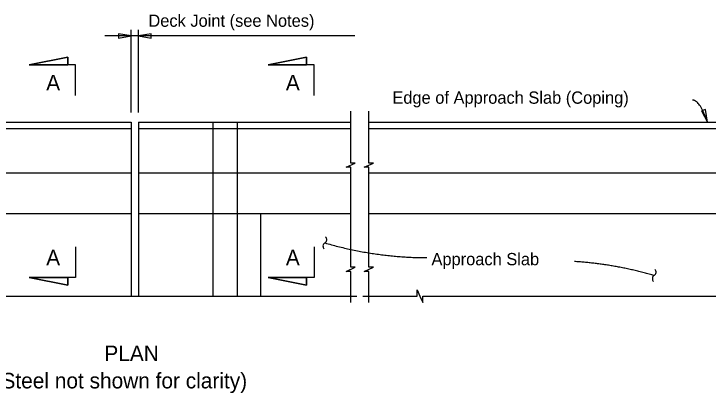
# Model space of a CAD drawing. Extents: x 0.5 to 40.8, y 1 to 25.8.
# Drawn here: x 18.01 to 29.41, y 19.47 to 25.71 of the extents above; entities that cross this region are included whole.
import ezdxf

# ---------------------------------------------------------------- set-up
doc = ezdxf.new("R2010")
doc.units = 0
for name, color, linetype in [('Dimension', 7, 'Continuous'), ('TextStructures', 7, 'Continuous'), ('TrafBarrierConc', 7, 'Continuous')]:
    doc.layers.add(name, color=color, linetype=linetype)

msp = doc.modelspace()

# ---------------------------------------------------------------- linework, layer by layer
at = {"layer": 'Dimension'}
for p, q in [((19.93, 24.083), (19.93, 25.443)), ((20.053, 24.083), (20.053, 25.443)), ((23.605, 25.342), (19.499, 25.342)), ((18.258, 24.868), (18.89, 24.995)), ((18.89, 24.995), (18.89, 24.868)), ((22.179, 24.868), (22.812, 24.995)), ((22.812, 24.995), (22.812, 24.868)), ((19.017, 24.868), (18.258, 24.868)), ((19.017, 24.362), (19.017, 24.868)), ((22.939, 24.868), (22.179, 24.868)), ((22.939, 24.362), (22.939, 24.868)), ((19.017, 21.876), (19.017, 21.369)), ((22.939, 21.876), (22.939, 21.369)), ((19.017, 21.369), (18.258, 21.369)), ((18.258, 21.369), (18.89, 21.243)), ((18.89, 21.243), (18.89, 21.369)), ((22.939, 21.369), (22.179, 21.369)), ((22.179, 21.369), (22.812, 21.243)), ((22.812, 21.243), (22.812, 21.369))]:
    msp.add_line(p, q, dxfattribs=at)
for points in [[(19.93, 25.342), (19.722, 25.377), (19.722, 25.306)], [(20.053, 25.342), (20.261, 25.306), (20.261, 25.377)], [(18.89, 24.868), (18.89, 24.995), (18.258, 24.868)], [(22.812, 24.868), (22.812, 24.995), (22.179, 24.868)], [(29.395, 23.924), (29.361, 24.132), (29.295, 24.11)], [(18.89, 21.369), (18.89, 21.243), (18.258, 21.369)], [(22.812, 21.369), (22.812, 21.243), (22.179, 21.369)]]:
    msp.add_lwpolyline(points, close=True, dxfattribs=at)
for points in [[(23.537, 22.14), (23.537, 23.186), (23.46, 23.186), (23.61, 23.252), (23.537, 23.252), (23.537, 24.107)], [(23.837, 22.14), (23.837, 23.186), (23.76, 23.186), (23.91, 23.252), (23.837, 23.252), (23.837, 24.107)], [(23.537, 20.963), (23.537, 21.472), (23.46, 21.472), (23.61, 21.539), (23.537, 21.539), (23.537, 22.14)], [(23.837, 20.963), (23.837, 21.472), (23.76, 21.472), (23.91, 21.539), (23.837, 21.539), (23.837, 22.14)], [(11.857, 21.063), (14.406, 21.063), (14.406, 21.167), (14.451, 21.063), (14.496, 20.96), (14.496, 21.063), (19.93, 21.063)], [(23.737, 21.063), (24.629, 21.063), (24.629, 21.167), (24.674, 21.063), (24.719, 20.96), (24.719, 21.063), (30.61, 21.063)], [(19.93, 21.063), (23.637, 21.063)]]:
    msp.add_lwpolyline(points, dxfattribs=at)
for centre, start, end in [((23.085, 21.992), 298.0989, 49.8261), ((23.141, 21.886), 118.0989, 229.8261), ((28.493, 21.458), 298.0989, 49.8261), ((28.549, 21.352), 118.0989, 229.8261)]:
    msp.add_arc(centre, 0.0596, start, end, dxfattribs=at)
for points in [[(29.395, 23.924), (29.272, 24.287), (29.149, 24.287)], [(23.113, 21.94), (23.95, 21.698), (24.788, 21.698)], [(28.521, 21.404), (27.865, 21.593), (27.209, 21.634)]]:
    msp.add_open_spline(points, degree=2, dxfattribs=at)
at = {"layer": 'TrafBarrierConc'}
for p, q in [((11.931, 23.924), (19.93, 23.924)), ((19.93, 23.924), (19.93, 21.063)), ((20.053, 23.924), (20.053, 21.063)), ((20.053, 23.924), (23.537, 23.924)), ((21.273, 23.924), (21.273, 21.063)), ((21.67, 23.924), (21.67, 21.063)), ((23.837, 23.924), (39.818, 23.924)), ((11.931, 23.82), (19.93, 23.82)), ((20.053, 23.82), (23.537, 23.82)), ((23.837, 23.82), (33.151, 23.82)), ((11.931, 23.091), (19.93, 23.091)), ((20.053, 23.091), (23.537, 23.091)), ((23.837, 23.091), (33.151, 23.091)), ((11.931, 22.424), (19.93, 22.424)), ((20.053, 22.424), (23.537, 22.424)), ((22.053, 22.424), (22.053, 21.063)), ((23.837, 22.424), (36.818, 22.424))]:
    msp.add_line(p, q, dxfattribs=at)

# ---------------------------------------------------------------- texts
at = {"layer": 'Dimension'}
for s, p in [('PLAN', (19.492, 19.996)), ('(Reinforcing Steel not shown for clarity)', (15.862, 19.548))]:
    msp.add_text(s, height=0.256, dxfattribs=at).set_placement(p)
at = {"layer": 'TextStructures'}
for s, height, p in [('Deck Joint (see Notes)', 0.2016, (20.215, 25.493)), ('A', 0.256, (18.537, 24.447)), ('A', 0.256, (22.472, 24.447)), ('Edge of Approach Slab (Coping)', 0.2016, (24.221, 24.228)), ('A', 0.256, (18.537, 21.571)), ('A', 0.256, (22.472, 21.571)), ('Approach Slab', 0.2016, (24.863, 21.573))]:
    msp.add_text(s, height=height, dxfattribs=at).set_placement(p)

doc.saveas('drawing.dxf')
